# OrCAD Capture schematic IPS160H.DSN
size C
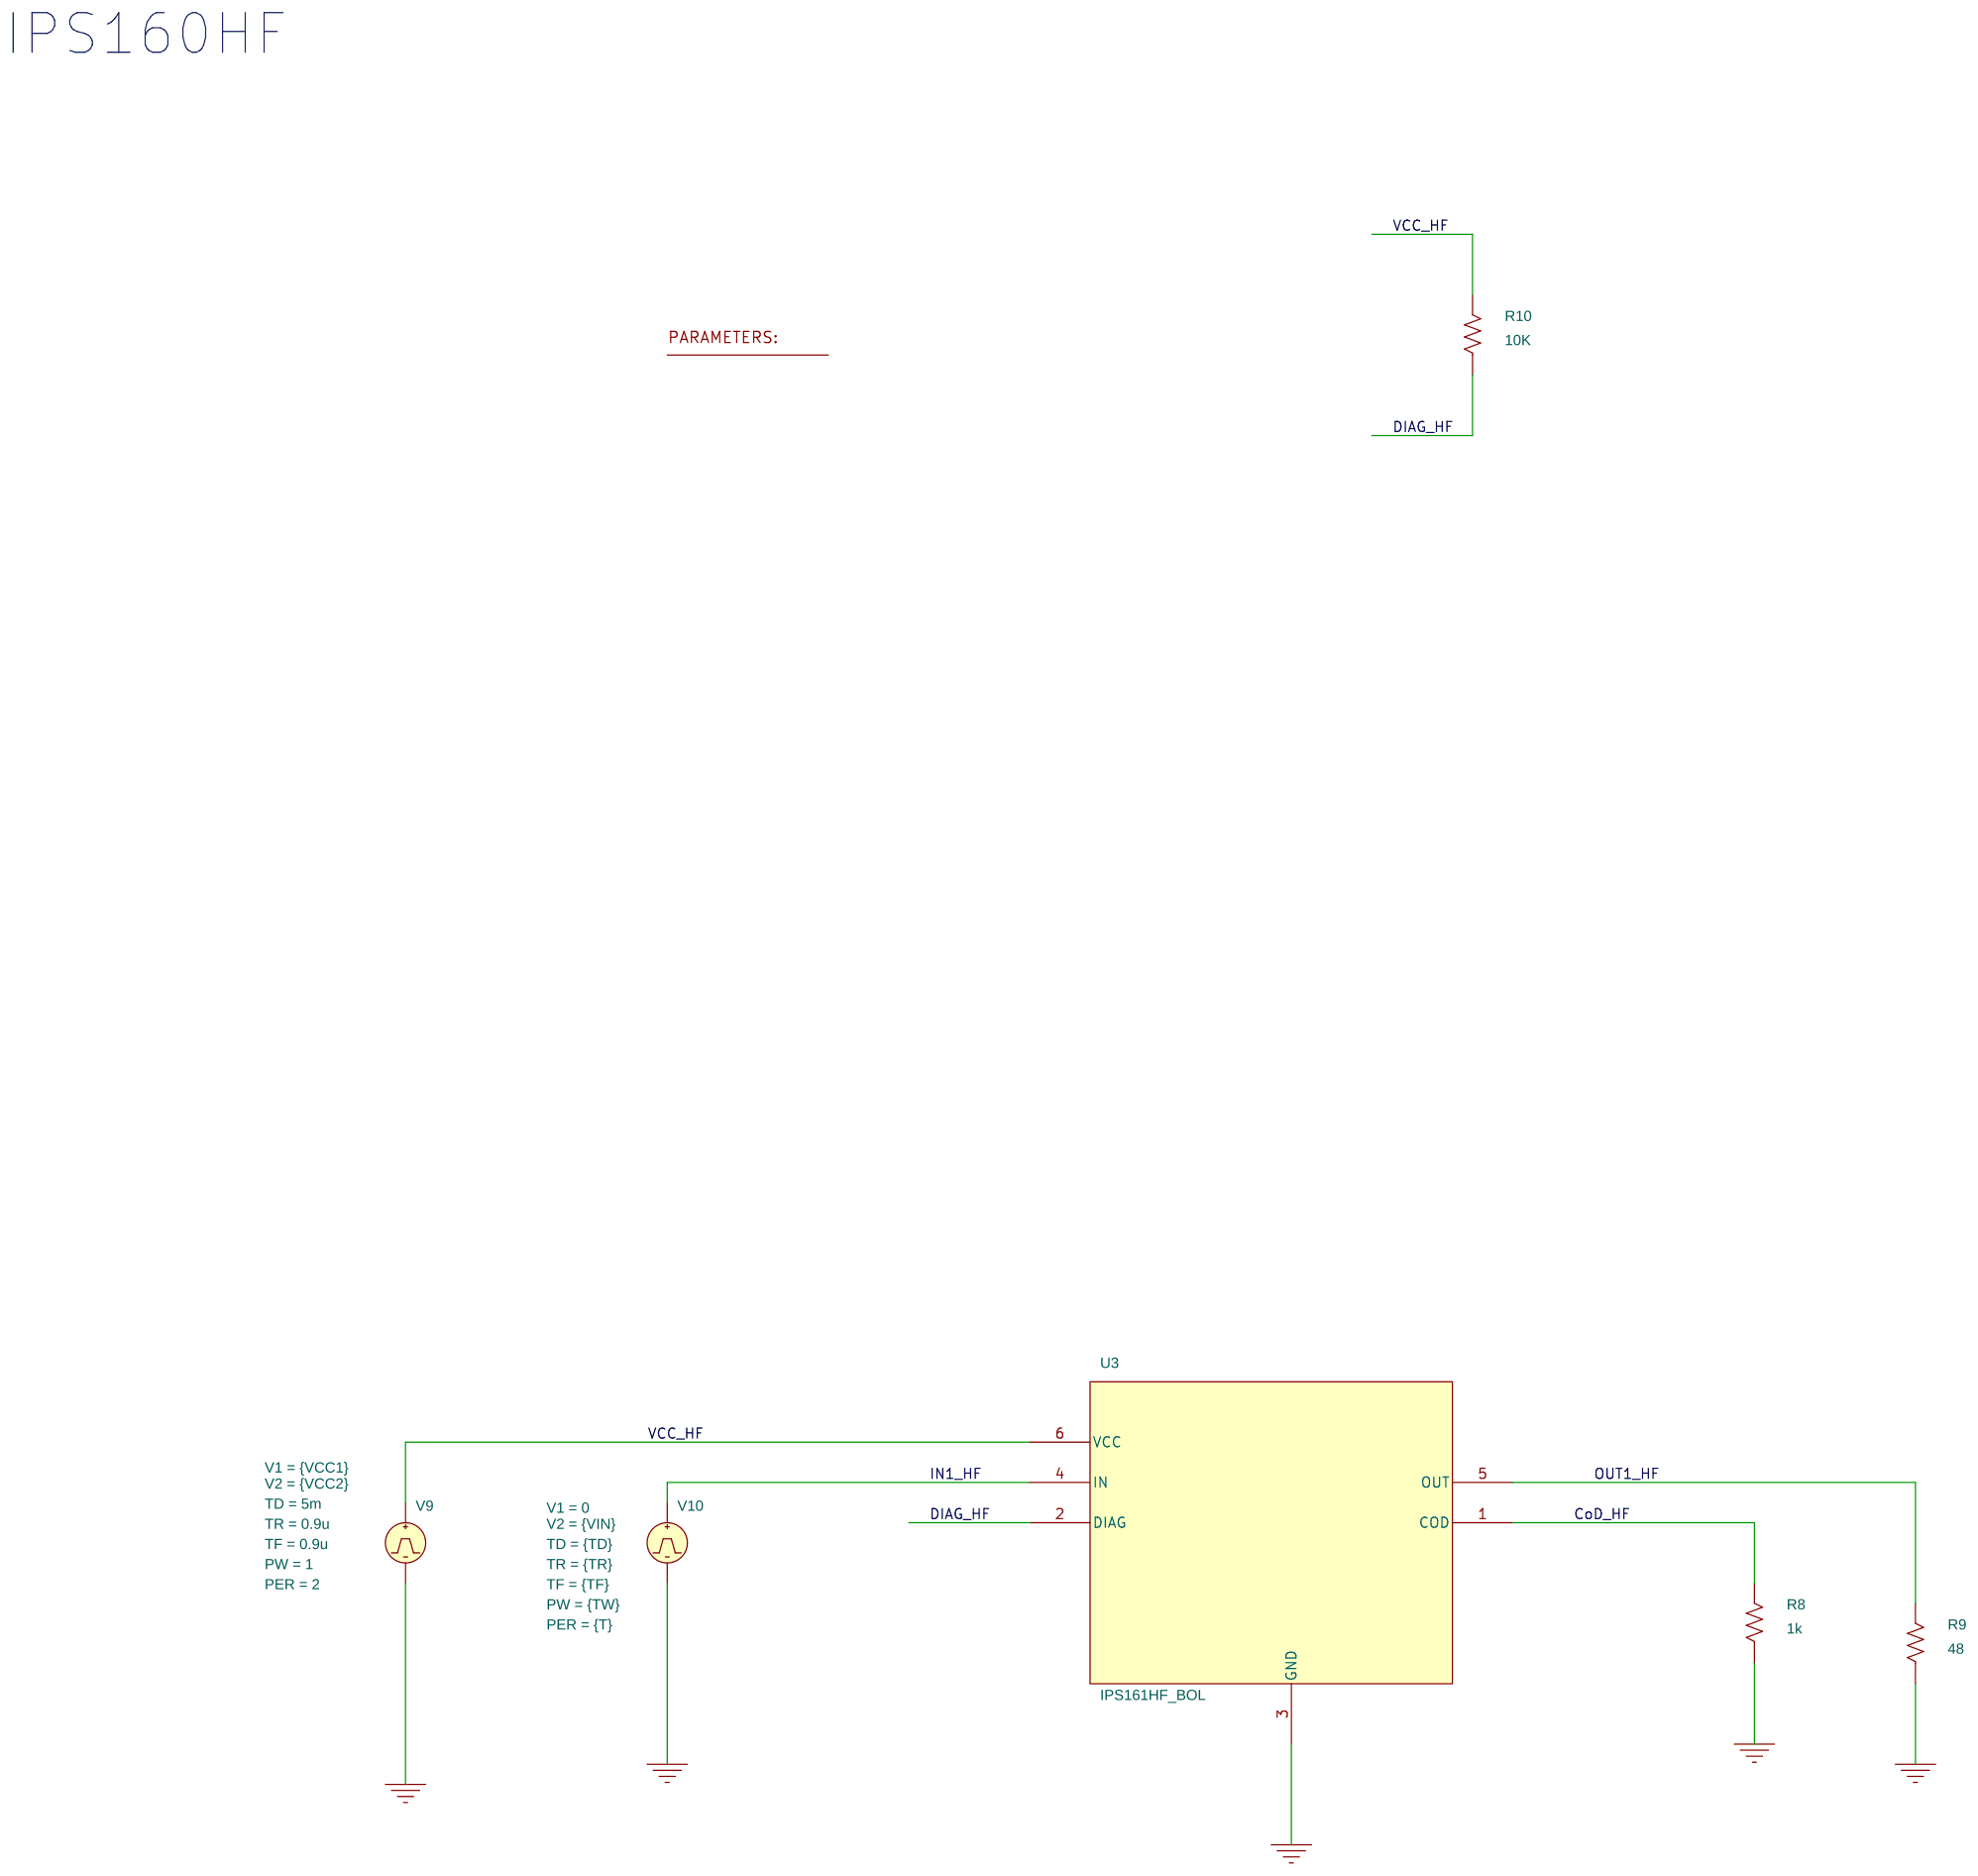
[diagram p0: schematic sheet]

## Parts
1  PARAM
R8  1k  [AX/RC05]
R9  48  [AX/RC05]
R10  10K  [AX/RC05]
U3  IPS161HF_BOL
V9  VPULSE
V10  VPULSE

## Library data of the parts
1 = PARAM: T: 200m; TD: 5m; TD2: 10m; TF: 0.09u; TR: 0.09u; TW: {0.8*T}; VCC1: 0; VCC2: 24; VIN: 3.3
R8-R10 = R
U3 = IPS161HF_BOL
V9 = VPULSE: PER: 2; PW: 1; TD: 5m; TF: 0.9u; TR: 0.9u; V1: {VCC1}; V2: {VCC2}
V10 = VPULSE: PER: {T}; PW: {TW}; TD: {TD}; TF: {TF}; TR: {TR}; V1: 0; V2: {VIN}

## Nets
VCC_HF: R10.2 U3.6(VCC) V9.1(+)
0: R8.1 R9.1 U3.3(GND) V9.2(-) V10.2(-)
CoD_HF: R8.2 U3.1(COD)
DIAG_HF: R10.1 U3.2(DIAG)
IN1_HF: U3.4(IN) V10.1(+)
OUT1_HF: R9.2 U3.5(OUT)

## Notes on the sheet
- IPS160HF
